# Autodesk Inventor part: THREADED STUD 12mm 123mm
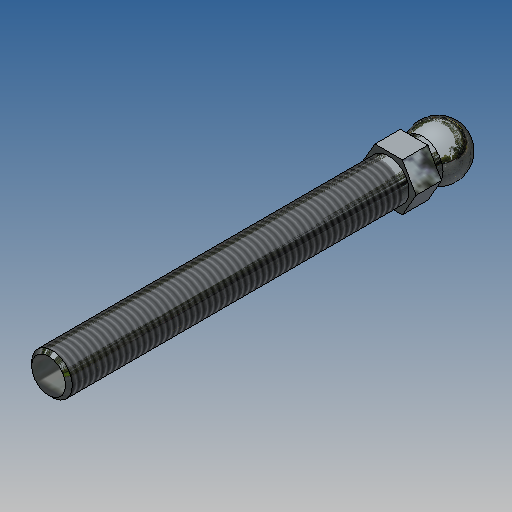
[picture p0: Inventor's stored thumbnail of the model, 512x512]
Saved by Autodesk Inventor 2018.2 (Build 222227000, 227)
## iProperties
Created: 2007-03
Part Number: THREADED STUD 12mm 123mm
Document SubType Name: Modeling
Designer: Andy Moles
Material: Steel
Mass: 156.787 g
Surface Area: 68.4363 cm^2
Volume: 19.9729 cm^3
Density: 7.85 g/cm^3
Appearance: Zinc
Author: Andy Moles
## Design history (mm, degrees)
sketch "Sketch1"
  geometry: L1 (0, -7.5)-(0, 7.5); A1 r 7.5 centre (0, 0) between (0, -7.5) and (0, 7.5); 1 further point
  constraints: 2 end point, 2 point on circle, 1 centre point, 1 coincident, 1 midpoint, 1 vertical
  dimensions: "d5" = 15 distance of L1.start L1.end
revolve "Revolution1" sketch "Sketch1" stored, may be unused: angle "d1" = 90 deg
sketch "Sketch2"
  geometry: C1 r 6 at (0, 0); 1 further point
  constraints: 1 centre point, 1 coincident
  dimensions: "d2" = 12 diameter of C1
extrude "Extrusion1" join sketch "Sketch2" distance "d3" = 7; taper "d4" = 0 deg
sketch "Sketch3"
  geometry: L1 (-4.041, 7)-(4.041, 7); L2 (4.041, 7)-(8.083, 0); L3 (8.083, 0)-(4.041, -7); L4 (4.041, -7)-(-4.041, -7); L5 (-4.041, -7)-(-8.083, 0); L6 (-8.083, 0)-(-4.041, 7); C1 r 6 at (0, 0) reference; 1 further point
  constraints: 12 end point, 5 equal length, 1 horizontal, 1 horizontal alignment, 1 midpoint, 1 parallel, 1 vertical alignment
  dimensions: "d6" = 120 deg angle of L6 L5; "d7" = 120 deg angle of L1 L6; "d8" = 14 distance between parallel lines of L4 L1
extrude "Extrusion2" join sketch "Sketch3" distance "d9" = 7.5; taper "d10" = 0 deg
sketch "Sketch4"
  geometry: C1 r 6 at (0, 0); 1 further point
  constraints: 1 centre point, 1 coincident
  dimensions: "d11" = 12 diameter of C1
extrude "Extrusion3" join sketch "Sketch4" distance "d12" = 100; taper "d13" = 0 deg
thread "Thread1" dims "d14" = 147, "d15" = 2
chamfer "Chamfer1" distance "d16" = 1; stored, may be unused: second distance "d17" = 2, angle "d18" = 45 deg
body "Solid1"
